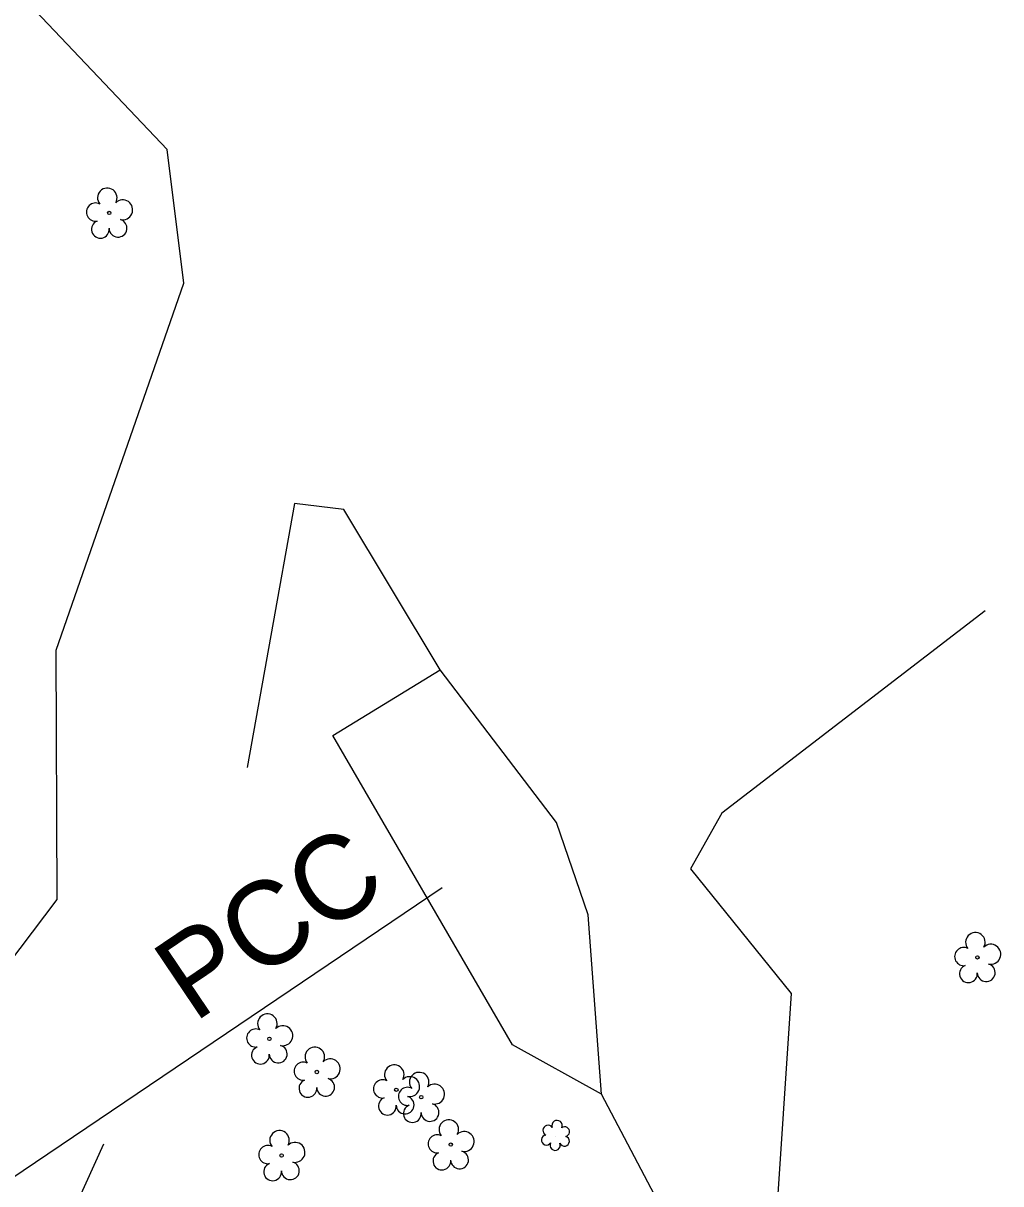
# Model space of a CAD drawing. Extents: x 474972 to 479313, y 498315 to 502691.
# Drawn here: x 476264.1 to 476450.2, y 501218.6 to 501439.4 of the extents above; entities that cross this region are included whole.
import ezdxf

# ---------------------------------------------------------------- set-up
doc = ezdxf.new("R2010")
doc.units = 0
for name, color, linetype in [('Exist Horizontal Alignment', 7, 'Continuous'), ('Exist Vegetation Hedge Row', 7, 'Continuous'), ('Exist Vegetation Shrub CELL', 7, 'Continuous'), ('Exist Vegetation Tree CELL', 7, 'Continuous'), ('Exist Vegetation Woods Line', 7, 'Continuous')]:
    doc.layers.add(name, color=color, linetype=linetype)

msp = doc.modelspace()

# ---------------------------------------------------------------- linework, layer by layer
at = {"layer": 'Exist Horizontal Alignment'}
msp.add_line((476244.33, 501207.83), (476343.85, 501274.95), dxfattribs=at)
at = {"layer": 'Exist Vegetation Hedge Row'}
msp.add_lwpolyline([(476374.17, 501235.67), (476357.21, 501245.04), (476323.03, 501303.89), (476343.44, 501316.35)], dxfattribs=at)
at = {"layer": 'Exist Vegetation Shrub CELL'}
msp.add_line((476365.47, 501227.63), (476365.47, 501227.63), dxfattribs=at)
for centre, radius, start, end in [((476363.99, 501228.75), 0.968, 35.8908, 245.4216), ((476365.7, 501229.67), 0.99, 334.8391, 200.4717), ((476363.67, 501226.92), 0.955, 95.1099, 327.9534), ((476367.11, 501226.7), 0.937, 204.9913, 73.4601), ((476367.14, 501228.5), 0.929, 284.4567, 126.0861), ((476365.34, 501225.94), 0.984, 151.2797, 21.387)]:
    msp.add_arc(centre, radius, start, end, dxfattribs=at)
at = {"layer": 'Exist Vegetation Tree CELL'}
for p, q in [((476280.48, 501403.31), (476280.48, 501403.31)), ((476445.71, 501261.67), (476445.71, 501261.67)), ((476310.96, 501246.18), (476310.96, 501246.18)), ((476319.99, 501239.87), (476319.99, 501239.87)), ((476335.11, 501236.49), (476335.11, 501236.49)), ((476339.86, 501235.07), (476339.86, 501235.07)), ((476345.48, 501226.05), (476345.48, 501226.05)), ((476313.28, 501223.98), (476313.28, 501223.98))]:
    msp.add_line(p, q, dxfattribs=at)
for centre in [(476280.48, 501403.31), (476445.71, 501261.67), (476310.96, 501246.18), (476319.99, 501239.87), (476335.11, 501236.49), (476339.86, 501235.07), (476345.48, 501226.05), (476313.28, 501223.98)]:
    msp.add_circle(centre, 0.326, dxfattribs=at)
for centre, radius, start, end in [((476280.1, 501406.19), 1.86, 330.1651, 219.7134), ((476277.87, 501403.47), 1.73, 62.6636, 279.3457), ((476283.03, 501403.9), 1.9, 257.1011, 134.1999), ((476282.15, 501400.42), 1.7, 181.2822, 74.56), ((476278.78, 501400.19), 1.69, 111.5671, 6.231), ((476445.33, 501264.54), 1.86, 330.1651, 219.7134), ((476443.11, 501261.82), 1.73, 62.6636, 279.3457), ((476448.26, 501262.26), 1.9, 257.1011, 134.1999), ((476444.01, 501258.55), 1.69, 111.5671, 6.231), ((476447.39, 501258.77), 1.7, 181.2822, 74.56), ((476310.58, 501249.05), 1.86, 330.1651, 219.7134), ((476308.36, 501246.33), 1.73, 62.6636, 279.3457), ((476313.51, 501246.77), 1.9, 257.1011, 134.1999), ((476309.26, 501243.06), 1.69, 111.5671, 6.231), ((476312.64, 501243.28), 1.7, 181.2822, 74.56), ((476319.6, 501242.74), 1.86, 330.1651, 219.7134), ((476317.38, 501240.02), 1.73, 62.6636, 279.3457), ((476322.54, 501240.46), 1.9, 257.1011, 134.1999), ((476334.73, 501239.36), 1.86, 330.1651, 219.7134), ((476321.66, 501236.97), 1.7, 181.2822, 74.56), ((476337.66, 501237.08), 1.9, 257.1011, 134.1999), ((476339.47, 501237.94), 1.86, 330.1651, 219.7134), ((476318.28, 501236.75), 1.69, 111.5671, 6.231), ((476332.51, 501236.64), 1.73, 62.6636, 279.3457), ((476337.25, 501235.23), 1.73, 62.6636, 279.3457), ((476342.4, 501235.66), 1.9, 257.1011, 134.1999), ((476333.41, 501233.37), 1.69, 111.5671, 6.231), ((476336.78, 501233.59), 1.7, 181.2822, 74.56), ((476338.15, 501231.95), 1.69, 111.5671, 6.231), ((476341.53, 501232.17), 1.7, 181.2822, 74.56), ((476345.1, 501228.92), 1.86, 330.1651, 219.7134), ((476312.89, 501226.86), 1.86, 330.1651, 219.7134), ((476342.88, 501226.2), 1.73, 62.6636, 279.3457), ((476348.03, 501226.63), 1.9, 257.1011, 134.1999), ((476310.67, 501224.14), 1.73, 62.6636, 279.3457), ((476315.83, 501224.57), 1.9, 257.1011, 134.1999), ((476343.78, 501222.92), 1.69, 111.5671, 6.231), ((476347.15, 501223.15), 1.7, 181.2822, 74.56), ((476311.57, 501220.86), 1.69, 111.5671, 6.231), ((476314.95, 501221.08), 1.7, 181.2822, 74.56)]:
    msp.add_arc(centre, radius, start, end, dxfattribs=at)
at = {"layer": 'Exist Vegetation Woods Line'}
for points in [[(476279.38, 501226.11), (476269.31, 501203.89), (476244.66, 501238.47), (476270.54, 501272.71), (476270.38, 501320.15), (476294.66, 501389.95), (476291.47, 501415.35), (476249.72, 501459.42), (476238.45, 501478.55), (476264.33, 501490.35), (476280.03, 501487.66), (476286.2, 501470.43), (476297.57, 501467.02), (476303.31, 501478), (476333.64, 501481.71), (476338.14, 501502.27)], [(476371.62, 501269.74), (476365.59, 501287.33), (476343.44, 501316.35), (476325.12, 501346.89), (476315.72, 501348.03), (476306.72, 501297.77)], [(476447.17, 501327.61), (476397.08, 501289.1), (476391.12, 501278.52)], [(476391.12, 501278.52), (476410.28, 501254.8), (476407.23, 501209.06)], [(476394.28, 501197.45), (476374.17, 501235.67), (476371.62, 501269.74)]]:
    msp.add_lwpolyline(points, dxfattribs=at)

# ---------------------------------------------------------------- texts
at = {"layer": 'Exist Horizontal Alignment'}
msp.add_text('PCC', height=16, rotation=33.9973, dxfattribs=at).set_placement((476296.58, 501249.1))

doc.saveas('drawing.dxf')
